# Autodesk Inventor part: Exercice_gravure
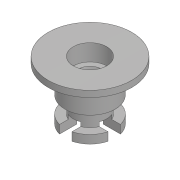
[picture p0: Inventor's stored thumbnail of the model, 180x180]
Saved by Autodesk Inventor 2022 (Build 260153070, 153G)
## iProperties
Created: 2018-06
Part Number: Exercice_gravure
Material: Plastique ABS
Document SubType Name: Modeling
Designer: Fabian Perrée
Density: 1.06 g/cm^3
Appearance: Gris clair
Author: Fabian Perrée
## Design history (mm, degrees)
sketch "Esquisse1"
  geometry: L1 (0, 0)-(0, 14); L2 (0, 14)-(10, 14); L3 (10, 14)-(10, 12.5); L4 (10, 12.5)-(6, 12.5); L5 (6, 12.5)-(6, 6); L6 (6, 6)-(4, 6); L7 (4, 6)-(4, 2); L8 (4, 2)-(6, 2); L9 (6, 2)-(6, 0); L10 (6, 0)-(0, 0); L11 (4, 14)-(4, 10); L12 (4, 10)-(2.25, 10); L13 (2.25, 10)-(2.25, 3); L14 (2.25, 3)-(0, 3)
  constraints: 28 end point, 12 perpendicular, 2 point on line, 2 vertical, 1 collinear
  dimensions: "d0" = 14 distance of L1.start L1.end; "d2" = 1.5 distance of L2.end L3.end; "d3" = 20 diameter of L3 L1; "d5" = 12 diameter of L5 L1; "d6" = 8 diameter of L7 L1; "d7" = 6.5 distance of L4.end L5.end; "d8" = 4 distance of L6.end L7.end; "d9" = 2 distance of L8.end L9.end (derived); "d10" = 8 diameter of L11 L1; "d11" = 4.5 diameter of L13 L1; "d12" = 4 distance of L11.start L11.end; "d13" = 3 distance between parallel lines of L10 L14
revolve "Révolution1" sketch "Esquisse1" stored, may be unused: angle "d14" = 90 deg
sketch "Esquisse2"
  geometry: L1 (6, 1.5)-(0, 1.5); L2 (0, 1.5)-(0, -1.5); L3 (0, -1.5)-(6, -1.5); L4 (6, -1.5)-(6, 1.5); L5 (0, 0)-(10, 0); C1 r 6 at (0, 0) reference; 1 further point
  constraints: 10 end point, 2 parallel, 1 horizontal, 1 horizontal alignment, 1 midpoint, 1 perpendicular, 1 tangent, 2 other
  dimensions: "d15" = 3 distance of L3.end L1.start
extrude "Extrusion1" cut sketch "Esquisse2" distance "d16" = 3; taper "d17" = 0 deg
pattern_circular "Réseau circulaire1" dims angle "d19" = 360 deg
chamfer "Chanfrein1" distance "d21" = 0.5; stored, may be unused: second distance "d22" = 2, angle "d23" = 45 deg
sketch "Esquisse3"
  geometry: C1 r 2.25 at (0, 0); A1 r 2.25 centre (0, 0) between (-1.5, -1.677) and (1.5, -1.677) reference
  constraints: 1 centre point, 1 coincident, 1 concentric
extrude "Extrusion2" cut sketch "Esquisse3" extent not by distance; stored distance "d24" = 10; taper "d25" = 0 deg
node "Solide1"
